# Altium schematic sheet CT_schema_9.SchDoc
size 274 x 160 mm
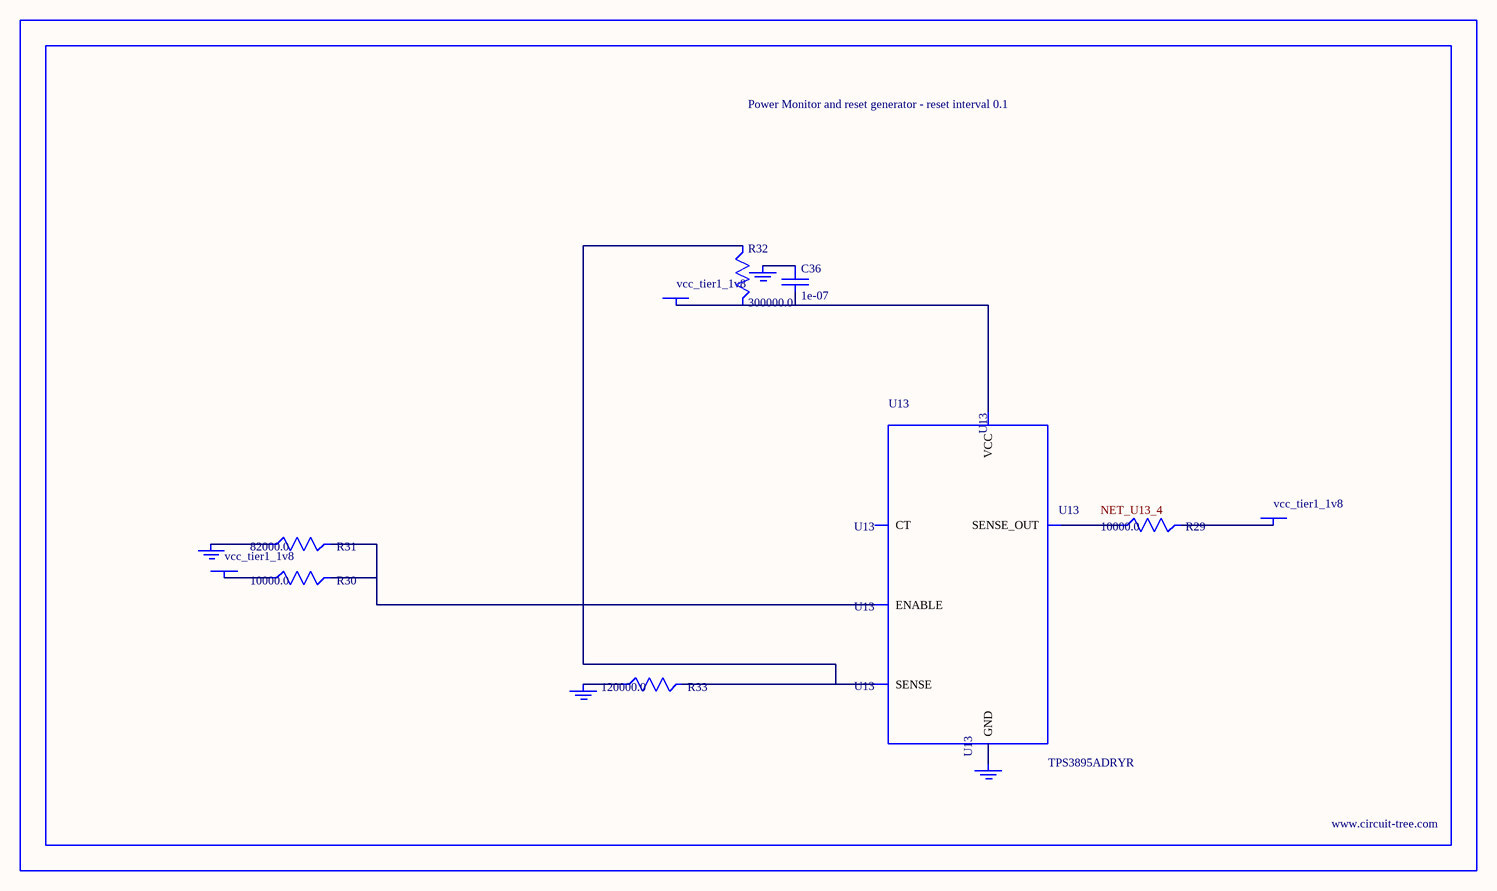
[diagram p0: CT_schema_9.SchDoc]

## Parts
BORDER8  (no value)
C36  1e-07  [C0402]
GND_INSTANCE_8_0  (no value)
GND_INSTANCE_8_1  (no value)
GND_INSTANCE_8_2  (no value)
GND_INSTANCE_8_3  (no value)
POWER_INSTANCE_8_0  vcc_tier1_1v8
POWER_INSTANCE_8_1  vcc_tier1_1v8
POWER_INSTANCE_8_2  vcc_tier1_1v8
R29  10000.0  [R0603]
R30  10000.0  [R0603]
R31  82000.0  [R0603]
R32  300000.0  [R0603]
R33  120000.0  [R0603]
U13  TPS3895ADRYR  [SON-6]

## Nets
NetC36_1: C36.1 GND_INSTANCE_8_2.0(GND)
NetC36_2: C36.2 POWER_INSTANCE_8_2.0(PWR) R32.2 U13.6(VCC)
NetGND_INSTANCE_8_0_0: GND_INSTANCE_8_0.0(GND) R31.1
NetGND_INSTANCE_8_1_0: GND_INSTANCE_8_1.0(GND) R33.1
NetGND_INSTANCE_8_3_0: GND_INSTANCE_8_3.0(GND) U13.2(GND)
NetPOWER_INSTANCE_8_0_0: POWER_INSTANCE_8_0.0(PWR) R30.1
NetPOWER_INSTANCE_8_1_0: POWER_INSTANCE_8_1.0(PWR) R29.2
NetR29_1: R29.1 U13.4(SENSE_OUT)
NetR30_2: R30.2 R31.2 U13.1(ENABLE)
NetR32_1: R32.1 R33.2 U13.3(SENSE)

Not connected (* = marked no-connect by the designer): U13 5(CT)

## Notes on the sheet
- Labels drawn without touching a wire or pin: NET_U13_4

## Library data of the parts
BORDER8 = BORDER_PAGE8
C36 = C0402C104K3RACTU
GND_INSTANCE_8_0-GND_INSTANCE_8_3 = GND
POWER_INSTANCE_8_0-POWER_INSTANCE_8_2 = PWR
R29 R30 = RC0603JR-0710KL
R31 = RC0603JR-0782KL
R32 = RC0603JR-07300KL
R33 = RC0603JR-07120KL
